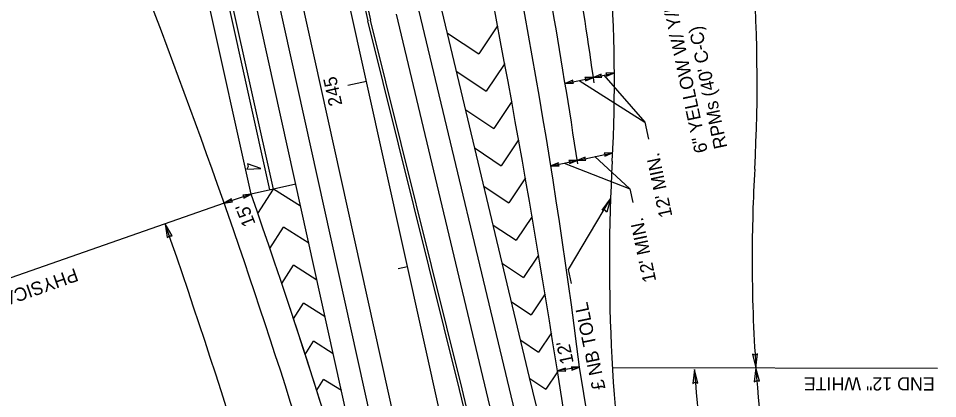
# Model space of a CAD drawing. Extents: x 578088 to 579220, y 1508751 to 1510400.
# Drawn here: x 578348.8 to 578831.9, y 1509387.9 to 1509588 of the extents above; entities that cross this region are included whole.
import ezdxf

# ---------------------------------------------------------------- set-up
doc = ezdxf.new("R2010")
doc.units = 0
for name, color, linetype in [('1', 7, 'Continuous'), ('18', 7, 'Continuous'), ('2', 7, 'Continuous'), ('28', 7, 'Continuous'), ('41', 7, 'Continuous'), ('46', 7, 'Continuous'), ('52', 7, 'Continuous'), ('8', 7, 'Continuous')]:
    doc.layers.add(name, color=color, linetype=linetype)

msp = doc.modelspace()

# ---------------------------------------------------------------- linework, layer by layer
at = {"layer": '1'}
for p, q in [((578639.69, 1509066.69), (578362.17, 1510321.74)), ((578559.88, 1509205.29), (578315.3, 1510311.37))]:
    msp.add_line(p, q, dxfattribs=at)
at = {"layer": '18'}
for p, q in [((578471.12, 1509495.56), (578291.87, 1510306.19)), ((578659.48, 1508810.53), (578375.62, 1510094.27)), ((578663.47, 1509155.01), (578558.43, 1509596.29)), ((578617.48, 1509399.06), (578570.71, 1509595.56)), ((578600.62, 1509584.1), (578590.78, 1509569.34)), ((578574.34, 1509580.3), (578590.78, 1509569.34)), ((578604.36, 1509564.21), (578594.7, 1509549.73)), ((578579.15, 1509560.1), (578594.7, 1509549.73)), ((578608.04, 1509544.24), (578598.62, 1509530.12)), ((578583.96, 1509539.9), (578598.62, 1509530.12)), ((578588.77, 1509519.69), (578602.54, 1509510.51)), ((578611.66, 1509524.18), (578602.54, 1509510.51)), ((578615.22, 1509504.03), (578606.47, 1509490.9)), ((578474.7, 1509485.28), (578482.83, 1509498.15)), ((578497.12, 1509489.12), (578482.83, 1509498.15)), ((578593.58, 1509499.49), (578606.47, 1509490.9)), ((578618.73, 1509483.8), (578610.39, 1509471.28)), ((578481.01, 1509466.91), (578488.1, 1509478.13)), ((578501.41, 1509469.72), (578488.1, 1509478.13)), ((578598.39, 1509479.28), (578610.39, 1509471.28)), ((578622.17, 1509463.47), (578614.31, 1509451.67)), ((578487.25, 1509448.44), (578493.37, 1509458.11)), ((578505.7, 1509450.31), (578493.37, 1509458.11)), ((578603.2, 1509459.08), (578614.31, 1509451.67)), ((578625.56, 1509443.05), (578618.23, 1509432.06)), ((578493.43, 1509429.86), (578498.64, 1509438.09)), ((578509.99, 1509430.91), (578498.64, 1509438.09)), ((578608.01, 1509438.88), (578618.23, 1509432.06)), ((578612.82, 1509418.67), (578622.15, 1509412.45)), ((578628.88, 1509422.55), (578622.15, 1509412.45)), ((578632.08, 1509402.54), (578629.57, 1509418.27)), ((578499.53, 1509411.16), (578503.9, 1509418.07)), ((578514.28, 1509411.51), (578503.9, 1509418.07)), ((578672.16, 1509226.28), (578643.76, 1509404.4)), ((578663.36, 1509206.35), (578617.48, 1509399.06)), ((578632.17, 1509401.98), (578626.07, 1509392.84)), ((578663.36, 1509206.35), (578632.08, 1509402.54)), ((578505.57, 1509392.36), (578509.17, 1509398.05)), ((578518.57, 1509392.11), (578509.17, 1509398.05)), ((578617.63, 1509398.47), (578626.07, 1509392.84))]:
    msp.add_line(p, q, dxfattribs=at)
for centre, radius, start, end in [((572971.29, 1508516.11), 5729.75, 9.059044, 12.468543), ((575170.03, 1508961.26), 3501.88, 7.26981, 13.05836), ((577905.47, 1509554.62), 756.56, 356.83788, 12.46827), ((573733.32, 1508756.06), 4967.27, 8.74692, 10.79232), ((573710.87, 1508850.29), 4990.37, 8.10796, 9.60928), ((579629.37, 1509459.39), 969.97, 176.83826, 189.05927)]:
    msp.add_arc(centre, radius, start, end, dxfattribs=at)
at = {"layer": '2'}
for p, q in [((578480.88, 1509497.72), (578301.64, 1510308.35)), ((578482.83, 1509498.15), (578303.59, 1510308.78)), ((578651.7, 1509152.41), (578547.48, 1509590.23))]:
    msp.add_line(p, q, dxfattribs=at)
at = {"layer": '28'}
for p, q in [((578531.74, 1509554.89), (578521.97, 1509552.74)), ((578494.55, 1509500.75), (578471.12, 1509495.56)), ((578553.33, 1509457.25), (578548.45, 1509456.17))]:
    msp.add_line(p, q, dxfattribs=at)
at = {"layer": '41'}
for p, q in [((578671.2, 1508813.02), (578338.64, 1510317)), ((578423.98, 1509581.25), (578387.22, 1509678.44))]:
    msp.add_line(p, q, dxfattribs=at)
for centre, radius, start, end in [((577905.47, 1509554.62), 756.56, 356.83788, 12.46827), ((577905.47, 1509554.62), 756.56, 356.83788, 12.46827), ((574851.28, 1508229.92), 3819.72, 12.46859, 20.71859), ((579629.37, 1509459.39), 969.97, 176.83826, 189.05927), ((579629.37, 1509459.39), 969.97, 176.83826, 189.05927), ((574851.28, 1508229.92), 3834.72, 14.7352, 19.27173)]:
    msp.add_arc(centre, radius, start, end, dxfattribs=at)
at = {"layer": '46'}
for p, q in [((578478.37, 1509830.99), (578532.36, 1509586.8)), ((578479.83, 1509831.31), (578533.83, 1509587.12)), ((578580.62, 1509392.73), (578532.36, 1509586.8)), ((578582.08, 1509393.05), (578533.83, 1509587.12)), ((578632.73, 1509173.81), (578580.62, 1509392.73)), ((578634.19, 1509174.14), (578582.08, 1509393.05))]:
    msp.add_line(p, q, dxfattribs=at)
at = {"layer": '52'}
for p, q in [((578650.95, 1509556.96), (578662.01, 1509559.31)), ((578655.03, 1509558.69), (578650.96, 1509556.96)), ((578654.88, 1509557.83), (578655.03, 1509558.69)), ((578662.01, 1509559.31), (578657.58, 1509559.19)), ((578657.58, 1509559.19), (578658.09, 1509558.44)), ((578657.94, 1509557.58), (578662.01, 1509559.31)), ((578658.09, 1509558.44), (578657.94, 1509557.58)), ((578636.12, 1509553.81), (578650.95, 1509556.96)), ((578640.19, 1509555.54), (578636.12, 1509553.81)), ((578636.12, 1509553.81), (578640.54, 1509553.92)), ((578640.04, 1509554.67), (578640.19, 1509555.54)), ((578640.54, 1509553.92), (578640.04, 1509554.67)), ((578643.54, 1509555.38), (578678.08, 1509533.36)), ((578650.96, 1509556.96), (578646.53, 1509556.84)), ((578646.53, 1509556.84), (578647.03, 1509556.09)), ((578646.88, 1509555.23), (578650.96, 1509556.96)), ((578647.03, 1509556.09), (578646.88, 1509555.23)), ((578650.96, 1509556.96), (578655.38, 1509557.08)), ((578655.38, 1509557.08), (578654.88, 1509557.83)), ((578656.48, 1509558.13), (578678.08, 1509533.36)), ((578678.08, 1509533.36), (578679.96, 1509524.51)), ((578642.53, 1509513.31), (578661.1, 1509517.26)), ((578646.61, 1509515.04), (578642.53, 1509513.31)), ((578646.46, 1509514.18), (578646.61, 1509515.04)), ((578651.82, 1509515.28), (578670.09, 1509498.39)), ((578661.1, 1509517.26), (578656.67, 1509517.14)), ((578656.67, 1509517.14), (578657.18, 1509516.39)), ((578657.03, 1509515.53), (578661.1, 1509517.26)), ((578657.18, 1509516.39), (578657.03, 1509515.53)), ((578469.6, 1509509.99), (578468.85, 1509508.74)), ((578476.22, 1509508.99), (578469.27, 1509511.46)), ((578469.27, 1509511.46), (578469.6, 1509509.99)), ((578628.6, 1509510.35), (578642.53, 1509513.31)), ((578632.67, 1509512.08), (578628.6, 1509510.35)), ((578628.6, 1509510.35), (578633.03, 1509510.47)), ((578632.52, 1509511.22), (578632.67, 1509512.08)), ((578633.03, 1509510.47), (578632.52, 1509511.22)), ((578635.57, 1509511.83), (578670.09, 1509498.39)), ((578642.53, 1509513.31), (578638.11, 1509513.19)), ((578638.11, 1509513.19), (578638.61, 1509512.44)), ((578638.46, 1509511.58), (578642.53, 1509513.31)), ((578638.61, 1509512.44), (578638.46, 1509511.58)), ((578642.53, 1509513.31), (578646.96, 1509513.43)), ((578646.96, 1509513.43), (578646.46, 1509514.18)), ((578468.85, 1509508.74), (578476.22, 1509508.99)), ((578471.12, 1509495.56), (578456.88, 1509490.85)), ((578471.12, 1509495.56), (578466.72, 1509494.99)), ((578467.24, 1509493.43), (578471.12, 1509495.56)), ((578670.09, 1509498.39), (578671.64, 1509491.09)), ((578456.88, 1509490.85), (578256.98, 1509420.69)), ((578460.75, 1509492.98), (578456.88, 1509490.85)), ((578456.88, 1509490.85), (578461.27, 1509491.42)), ((578460.69, 1509492.11), (578460.75, 1509492.98)), ((578461.27, 1509491.42), (578460.69, 1509492.11)), ((578466.72, 1509494.99), (578467.3, 1509494.3)), ((578467.3, 1509494.3), (578467.24, 1509493.43)), ((578637.94, 1509455.95), (578659.98, 1509493.1)), ((578655.63, 1509487.15), (578659.98, 1509493.1)), ((578659.98, 1509493.1), (578658.11, 1509485.96)), ((578657.09, 1509487.06), (578655.63, 1509487.15)), ((578658.11, 1509485.96), (578657.09, 1509487.06)), ((578425.94, 1509479.99), (578426.99, 1509472.68)), ((578429.59, 1509473.58), (578425.94, 1509479.99)), ((578426.99, 1509472.68), (578428.14, 1509473.66)), ((578428.14, 1509473.66), (578429.59, 1509473.58)), ((578639.53, 1509448.5), (578637.94, 1509455.95)), ((578735.94, 1509410.86), (578734.56, 1509411.32)), ((578734.56, 1509411.32), (578736.39, 1509404.17)), ((578737.3, 1509411.5), (578735.94, 1509410.86)), ((578736.39, 1509404.17), (578737.3, 1509411.5)), ((578643.76, 1509404.4), (578632.08, 1509402.53)), ((578636.24, 1509404.02), (578632.08, 1509402.53)), ((578636.05, 1509403.17), (578636.24, 1509404.02)), ((578643.76, 1509404.4), (578639.33, 1509404.54)), ((578639.33, 1509404.54), (578639.79, 1509403.77)), ((578639.59, 1509402.91), (578643.76, 1509404.4)), ((578639.79, 1509403.77), (578639.59, 1509402.91)), ((578660.96, 1509404.36), (578831.89, 1509403.94)), ((578736.39, 1509404.17), (578735.5, 1509396.84)), ((578738.24, 1509397.03), (578736.39, 1509404.17)), ((578632.08, 1509402.53), (578636.5, 1509402.39)), ((578636.5, 1509402.39), (578636.05, 1509403.17)), ((578704.08, 1509403.22), (578703.18, 1509395.89)), ((578705.92, 1509396.08), (578704.08, 1509403.22)), ((578703.18, 1509395.89), (578704.54, 1509396.54)), ((578704.54, 1509396.54), (578705.92, 1509396.08)), ((578735.5, 1509396.84), (578736.86, 1509397.49)), ((578736.86, 1509397.49), (578738.24, 1509397.03))]:
    msp.add_line(p, q, dxfattribs=at)
for centre, radius, start, end in [((577905.47, 1509554.62), 831.56, 356.83788, 12.46827), ((579629.37, 1509459.39), 894.97, 176.83826, 179.86066), ((574817.44, 1508227.41), 3819.72, 14.68854, 19.14283), ((579551.42, 1509461.18), 817.02, 179.97294, 184.00099), ((579703.85, 1509473.98), 969.97, 184.12715, 189.05927), ((579703.85, 1509473.98), 1002.26, 184.12715, 189.05927)]:
    msp.add_arc(centre, radius, start, end, dxfattribs=at)
at = {"layer": '8'}
msp.add_arc((574851.28, 1508229.92), 3834.72, 15.5225, 18.32289, dxfattribs=at)

# ---------------------------------------------------------------- texts
at = {"layer": '28'}
msp.add_text('245', height=7, rotation=102.4686, dxfattribs=at).set_placement((578519.08, 1509542.68))
at = {"layer": '52'}
for s, rotation, p in [('6" YELLOW W/ Y/R', 102, (578711.15, 1509518)), ("RPMs (40' C-C)", 102, (578721.42, 1509520.19)), ("12' MIN.", 102, (578692.55, 1509483.99)), ("15'", 111.5948, (578473.56, 1509480)), ("12' MIN.", 102, (578684.06, 1509449.88)), ('PHYSICAL GORE', 199.3587, (578378.61, 1509456.73)), ('£ NB TOLL', 101.75, (578657.36, 1509393.26)), ("12'", 102, (578640.7, 1509406.81)), ('END 12" WHITE', 179.9855, (578830.39, 1509399.19))]:
    msp.add_text(s, height=7, rotation=rotation, dxfattribs=at).set_placement(p)

doc.saveas('drawing.dxf')
